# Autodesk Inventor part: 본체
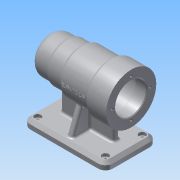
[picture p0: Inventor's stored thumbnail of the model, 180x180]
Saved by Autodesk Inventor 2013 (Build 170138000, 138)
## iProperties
Created: 2016-06
Part Number: 본체
Material: 알루미늄 6061
Document SubType Name: Modeling
Designer: Administrator
Density: 2.71 g/cm^3
Mass: 693.6 g
Surface Area: 666.256 cm^2
Volume: 255.941 cm^3
Author: Administrator
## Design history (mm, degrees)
sketch "스케치1"
  geometry: L1 (-46, 35)-(46, 35); L2 (56, 25)-(56, -25); L3 (46, -35)-(-46, -35); L4 (-56, -25)-(-56, 25); A1 r 10 centre (-46, 25) between (-46, 35) and (-56, 25); A2 r 10 centre (-46, -25) between (-56, -25) and (-46, -35); A3 r 10 centre (46, -25) between (46, -35) and (56, -25); A4 r 10 centre (46, 25) between (56, 25) and (46, 35); 3 further points
  constraints: 8 end point, 8 point on circle, 8 tangent, 4 centre point, 3 equal radius, 2 midpoint, 2 parallel, 1 horizontal, 1 horizontal alignment, 1 perpendicular, 1 vertical alignment
  dimensions: "d0" = 112 distance between parallel lines of L2 L4; "d2" = 70 distance between parallel lines of L1 L3; "d3" = 10 radius of A1
extrude "돌출1" new body sketch "스케치1" distance "d4" = 10; taper "d5" = 0 deg
sketch "스케치2"
  geometry: L1 (-56, 0)-(-56, 10) reference; L2 (-46, 10)-(-56, 10) reference; L3 (46, 10)-(-46, 10) reference; L4 (56, 10)-(46, 10) reference; L5 (56, 0)-(56, 10) reference; L6 (56, 0)-(46, 0) reference; L7 (46, 0)-(-46, 0) reference; L8 (-46, 0)-(-56, 0) reference; L9 (-56, 70)-(56, 70); L10 (56, 70)-(56, 104); L11 (56, 104)-(28, 104); L12 (28, 104)-(28, 100); L13 (28, 100)-(-11, 100); L14 (-11, 100)-(-11, 97); L15 (-11, 97)-(-31, 97); L16 (-31, 97)-(-31, 95); L17 (-31, 95)-(-46, 95); L18 (-56, 85)-(-56, 70); A1 r 10 centre (-46, 85) between (-46, 95) and (-56, 85); 1 further point
  constraints: 20 end point, 8 parallel, 2 perpendicular, 2 point on circle, 2 tangent, 1 centre point, 1 vertical alignment
  dimensions: "d6" = 112 distance of L9.start L9.end; "d9" = 25 distance between parallel lines of L18 L16; "d10" = 45 distance between parallel lines of L14 L18; "d11" = 84 distance between parallel lines of L12 L18; "d12" = 68 diameter of L11 L9; "d13" = 60 diameter of L13 L9; "d14" = 54 diameter of L15 L9; "d15" = 50 diameter of L17 L9; "d16" = 10 radius of A1; "d124" = 70 distance from line of L9.end L7
revolve "회전1" sketch "스케치2" stored, may be unused: angle "d17" = 90 deg
sketch "스케치3"
  geometry: L1 (-56, 55)-(-56, 85) reference; L2 (-46, 45)-(-31, 45) reference; L3 (-31, 43)-(-11, 43) reference; L4 (-11, 40)-(28, 40) reference; L5 (28, 36)-(56, 36) reference; L6 (46, 10)-(-46, 10) reference; L7 (-46, 10)-(-56, 10) reference; L8 (56, 10)-(46, 10) reference; L9 (-36, 10)-(-36, 65); L10 (-36, 65)-(36, 65); L11 (36, 65)-(36, 10); L12 (56, 36)-(56, 104) reference; L13 (56, 0)-(56, 10) reference; L14 (-56, 0)-(-56, 10) reference; A1 r 10 centre (-46, 85) between (-46, 95) and (-56, 85) reference; A2 r 10 centre (-46, 55) between (-56, 55) and (-46, 45) reference; 2 further points
  constraints: 6 end point, 3 perpendicular, 2 point on line, 1 midpoint, 1 vertical alignment
  dimensions: "d18" = 20 distance between parallel lines of L11 L13; "d19" = 55 distance between parallel lines of L6 L10
extrude "돌출2" join sketch "스케치3" stored distance "d20" = 8; taper "d21" = 0 deg
sketch "스케치4"
  geometry: L1 (25, 10)-(-25, 10) reference; L2 (-35, 0)-(-35, 10) reference; L3 (-25, 10)-(-35, 10) reference; L4 (35, 10)-(25, 10) reference; L5 (35, 0)-(35, 10) reference; L6 (35, 0)-(25, 0) reference; L7 (25, 0)-(-25, 0) reference; L8 (-25, 0)-(-35, 0) reference; L9 (-4, 36.236)-(-4, 10) reference; L10 (4, 10)-(4, 36.236) reference; L11 (-8.043, 64.83)-(8.043, 64.83); L12 (8.043, 64.83)-(28, 10); L13 (-8.043, 64.83)-(-28, 10); A1 r 34 centre (0, 70) between (4, 36.236) and (-4, 36.236) reference; 1 further point
  constraints: 6 end point, 2 point on line, 1 equal length, 1 perpendicular
  dimensions: "d23" = 7 distance from line of L12.end L5; "d24" = 7 distance from line of L13.end L2; "d25" = 110 deg angle of L13 L3; "d26" = 54.83005 distance between parallel lines of L1 L11
extrude "돌출3" join sketch "스케치4" stored distance "d28" = 8; taper "d29" = 0 deg
hole "구멍1" diameter "d32" = 42; stored, may be unused: countersink angle "d36" = 90 deg, drill point angle "d38" = 0 deg; dims "d30" = 10, "d31" = 10, "d33" = 6, "d34" = 4, "d35" = 2, "d37" = 15
hole "구멍2" diameter "d41" = 48; stored, may be unused: countersink angle "d45" = 90 deg, drill point angle "d47" = 0 deg; dims "d39" = 10, "d40" = 10, "d42" = 6, "d43" = 4, "d44" = 2, "d46" = 54
hole "구멍3" diameter "d50" = 42; stored, may be unused: countersink angle "d54" = 90 deg, drill point angle "d56" = 0 deg; dims "d48" = 10, "d49" = 10, "d51" = 6, "d52" = 4, "d53" = 2, "d55" = 12
hole "구멍4" diameter "d59" = 35; stored, may be unused: countersink angle "d63" = 90 deg, drill point angle "d65" = 0 deg; dims "d57" = 10, "d58" = 10, "d60" = 6, "d61" = 4, "d62" = 2, "d64" = 18
hole "구멍5" diameter "d68" = 32; stored, may be unused: countersink angle "d72" = 90 deg, drill point angle "d74" = 0 deg; dims "d66" = 10, "d67" = 10, "d69" = 6, "d70" = 4, "d71" = 2, "d73" = 4
hole "구멍6" diameter "d77" = 21; stored, may be unused: countersink angle "d81" = 90 deg, drill point angle "d83" = 0 deg; dims "d75" = 10, "d76" = 10, "d78" = 6, "d79" = 4, "d80" = 2, "d82" = 3
sketch "스케치5"
  geometry: A1 r 34 centre (0, 0) between (-33.764, -4) and (-33.764, 4) reference; 2 further points
  constraints: 1 horizontal alignment
  dimensions: "d84" = 26 distance of point (-26, 0) A1.centre
hole "구멍7" sketch "스케치5" at (-26, 0) diameter "d85" = 3.242; stored, may be unused: countersink angle "d89" = 90 deg, drill point angle "d91" = 118 deg; dims "d86" = 8, "d87" = 4, "d88" = 2, "d90" = 11
sketch "스케치6"
  geometry: L1 (-56, 25)-(-56, -25) reference; L2 (46, 35)-(-46, 35) reference; L3 (56, -25)-(56, 25) reference; L4 (-46, -35)-(46, -35) reference; C1 r 4.5 at (-46, 25); C2 r 4.5 at (46, 25); C3 r 4.5 at (46, -25); C4 r 4.5 at (-46, -25); A1 r 10 centre (-46, 25) between (-46, 35) and (-56, 25) reference; A2 r 10 centre (46, 25) between (56, 25) and (46, 35) reference; A3 r 10 centre (46, -25) between (46, -35) and (56, -25) reference; A4 r 10 centre (-46, -25) between (-56, -25) and (-46, -35) reference; 1 further point
  constraints: 4 centre point, 3 equal radius, 2 horizontal alignment, 2 vertical alignment
  dimensions: "d95" = 92 distance of C3.centre C4.centre; "d97" = 50 distance of C4.centre C1.centre; "d98" = 25 vertical distance of C1.centre point (0, 0); "d99" = 46 horizontal distance of point (0, 0) C2.centre; "d100" = 9 diameter of C1
hole "구멍8" sketch "스케치6" at (46, -25), (-46, 25), (46, 25), (-46, -25) diameter "d101" = 5; stored, may be unused: countersink angle "d105" = 90 deg, drill point angle "d107" = 0 deg; dims "d102" = 8, "d103" = 9, "d104" = 4, "d106" = 11
chamfer "모따기1" distance "d108" = 4; stored, may be unused: second distance "d109" = 2, angle "d110" = 45 deg
chamfer "모따기2" distance "d111" = 1; stored, may be unused: second distance "d112" = 2, angle "d113" = 45 deg
fillet "모깎기1" dims "d114" = 0.3
fillet "모깎기2" dims "d115" = 3
fillet "모깎기3" dims "d116" = 3
fillet "모깎기4" dims "d117" = 3
fillet "모깎기5" dims "d118" = 3
fillet "모깎기6" dims "d119" = 3
node "작업 평면1"
sketch "스케치7"
  geometry: L1 (56, 36)-(56, 104) reference; 3 further points
  constraints: 1 horizontal alignment, 1 midpoint, 1 other
  dimensions: "d121" = 48 distance from line of point (8, 70) L1
feature "엠보싱1" sketch "스케치7" dims "d0" = 112, "d122" = 0.5, "d123" = 0
node "솔리드1"
pattern_circular "원형 패턴1" dims angle "d93" = 360 deg
node "투영된 루프1"
other parameters: "d27" = 8
